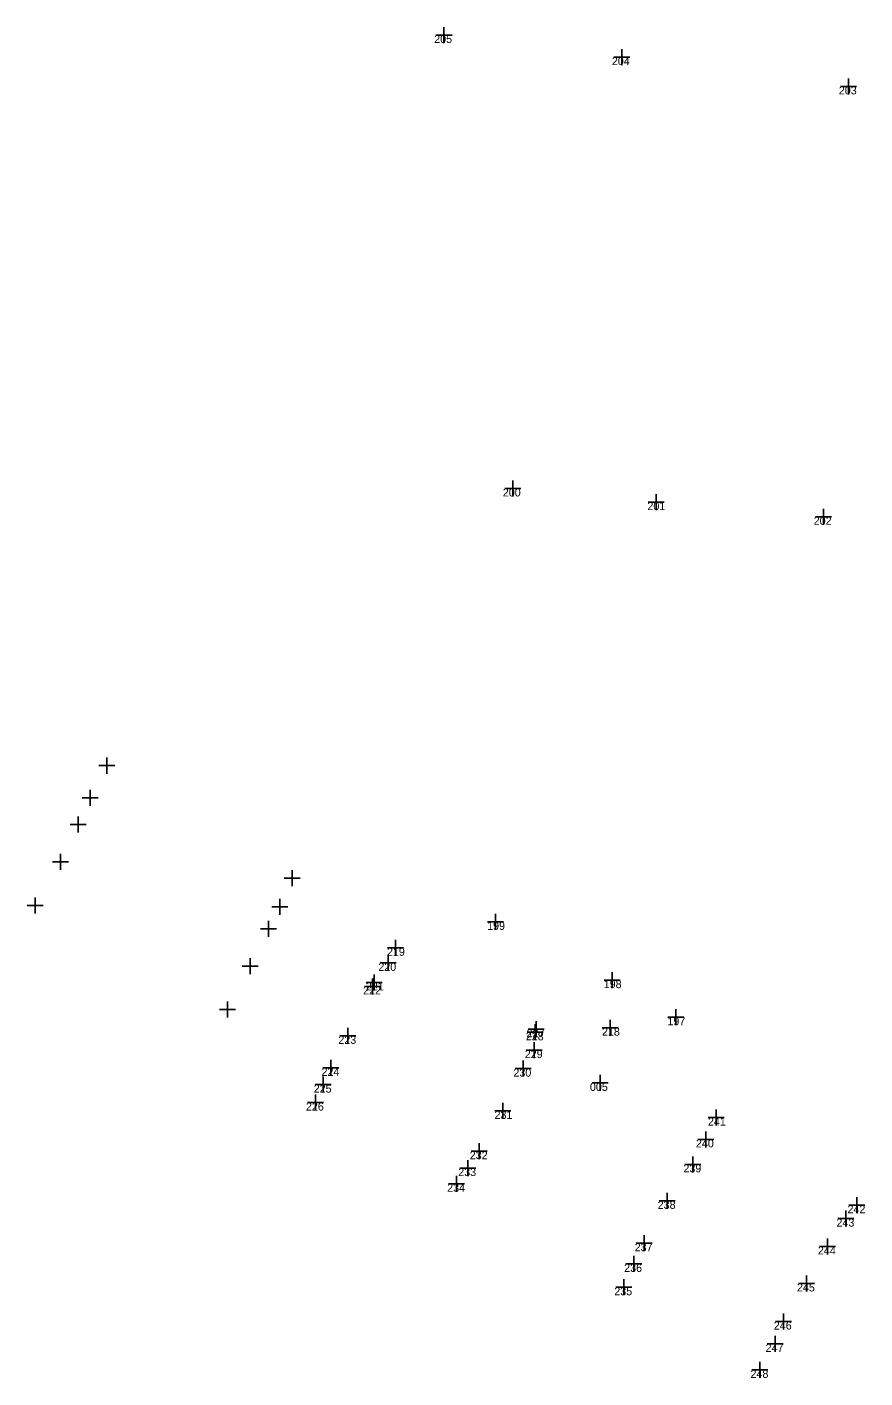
# Model space of a CAD drawing. Extents: x -706631 to -706106, y -1036183 to -1035074.
# Drawn here: x -706294.5 to -706242.2, y -1036182.5 to -1036098.1 of the extents above; entities that cross this region are included whole.
import ezdxf

# ---------------------------------------------------------------- set-up
doc = ezdxf.new("R2010")
doc.units = 0
doc.layers.add('čísla bodu', color=7, linetype='Continuous')

msp = doc.modelspace()

# ---------------------------------------------------------------- linework, layer by layer
at = {"layer": 'čísla bodu'}
for p, q in [((-706268.95, -1036098.6), (-706267.95, -1036098.6)), ((-706268.45, -1036099.1), (-706268.45, -1036098.1)), ((-706268.45, -1036098.6), (-706268.45, -1036098.6)), ((-706257.35, -1036100.48), (-706257.35, -1036099.48)), ((-706257.85, -1036099.98), (-706256.85, -1036099.98)), ((-706257.35, -1036099.98), (-706257.35, -1036099.98)), ((-706243.17, -1036102.31), (-706243.17, -1036101.31)), ((-706243.67, -1036101.81), (-706242.67, -1036101.81)), ((-706243.17, -1036101.81), (-706243.17, -1036101.81)), ((-706264.14, -1036127.43), (-706264.14, -1036126.43)), ((-706264.64, -1036126.93), (-706263.64, -1036126.93)), ((-706264.14, -1036126.93), (-706264.14, -1036126.93)), ((-706255.2, -1036128.28), (-706255.2, -1036127.28)), ((-706255.7, -1036127.78), (-706254.7, -1036127.78)), ((-706255.2, -1036127.78), (-706255.2, -1036127.78)), ((-706244.74, -1036129.2), (-706244.74, -1036128.2)), ((-706245.24, -1036128.7), (-706244.24, -1036128.7)), ((-706244.74, -1036128.7), (-706244.74, -1036128.7)), ((-706290.01, -1036144.25), (-706289.01, -1036144.25)), ((-706290.01, -1036144.25), (-706289.01, -1036144.25)), ((-706289.51, -1036144.75), (-706289.51, -1036143.75)), ((-706289.51, -1036144.75), (-706289.51, -1036143.75)), ((-706289.51, -1036144.25), (-706289.51, -1036144.25)), ((-706289.51, -1036144.25), (-706289.51, -1036144.25)), ((-706290.56, -1036146.76), (-706290.56, -1036145.76)), ((-706290.56, -1036146.76), (-706290.56, -1036145.76)), ((-706291.06, -1036146.26), (-706290.06, -1036146.26)), ((-706291.06, -1036146.26), (-706290.06, -1036146.26)), ((-706290.56, -1036146.26), (-706290.56, -1036146.26)), ((-706290.56, -1036146.26), (-706290.56, -1036146.26)), ((-706291.3, -1036148.43), (-706291.3, -1036147.43)), ((-706291.3, -1036148.43), (-706291.3, -1036147.43)), ((-706291.8, -1036147.93), (-706290.8, -1036147.93)), ((-706291.8, -1036147.93), (-706290.8, -1036147.93)), ((-706291.3, -1036147.93), (-706291.3, -1036147.93)), ((-706291.3, -1036147.93), (-706291.3, -1036147.93)), ((-706292.9, -1036150.26), (-706291.9, -1036150.26)), ((-706292.9, -1036150.26), (-706291.9, -1036150.26)), ((-706292.4, -1036150.76), (-706292.4, -1036149.76)), ((-706292.4, -1036150.76), (-706292.4, -1036149.76)), ((-706292.4, -1036150.26), (-706292.4, -1036150.26)), ((-706292.4, -1036150.26), (-706292.4, -1036150.26)), ((-706277.93, -1036151.77), (-706277.93, -1036150.77)), ((-706277.93, -1036151.77), (-706277.93, -1036150.77)), ((-706278.43, -1036151.27), (-706277.43, -1036151.27)), ((-706278.43, -1036151.27), (-706277.43, -1036151.27)), ((-706277.93, -1036151.27), (-706277.93, -1036151.27)), ((-706277.93, -1036151.27), (-706277.93, -1036151.27)), ((-706294, -1036153.49), (-706294, -1036152.49)), ((-706294, -1036153.49), (-706294, -1036152.49)), ((-706278.7, -1036153.57), (-706278.7, -1036152.57)), ((-706278.7, -1036153.57), (-706278.7, -1036152.57)), ((-706294.5, -1036152.99), (-706293.5, -1036152.99)), ((-706294.5, -1036152.99), (-706293.5, -1036152.99)), ((-706294, -1036152.99), (-706294, -1036152.99)), ((-706294, -1036152.99), (-706294, -1036152.99)), ((-706279.2, -1036153.07), (-706278.2, -1036153.07)), ((-706279.2, -1036153.07), (-706278.2, -1036153.07)), ((-706278.7, -1036153.07), (-706278.7, -1036153.07)), ((-706278.7, -1036153.07), (-706278.7, -1036153.07)), ((-706265.23, -1036154.51), (-706265.23, -1036153.51)), ((-706279.92, -1036154.44), (-706278.92, -1036154.44)), ((-706279.92, -1036154.44), (-706278.92, -1036154.44)), ((-706279.42, -1036154.94), (-706279.42, -1036153.94)), ((-706279.42, -1036154.94), (-706279.42, -1036153.94)), ((-706279.42, -1036154.44), (-706279.42, -1036154.44)), ((-706279.42, -1036154.44), (-706279.42, -1036154.44)), ((-706265.73, -1036154.01), (-706264.73, -1036154.01)), ((-706265.23, -1036154.01), (-706265.23, -1036154.01)), ((-706271.49, -1036156.13), (-706271.49, -1036155.13)), ((-706271.99, -1036155.63), (-706270.99, -1036155.63)), ((-706271.94, -1036157.07), (-706271.94, -1036156.07)), ((-706271.49, -1036155.63), (-706271.49, -1036155.63)), ((-706281.05, -1036156.78), (-706280.05, -1036156.78)), ((-706281.05, -1036156.78), (-706280.05, -1036156.78)), ((-706280.55, -1036157.28), (-706280.55, -1036156.28)), ((-706280.55, -1036157.28), (-706280.55, -1036156.28)), ((-706280.55, -1036156.78), (-706280.55, -1036156.78)), ((-706280.55, -1036156.78), (-706280.55, -1036156.78)), ((-706272.44, -1036156.57), (-706271.44, -1036156.57)), ((-706271.94, -1036156.57), (-706271.94, -1036156.57)), ((-706273.31, -1036157.79), (-706272.31, -1036157.79)), ((-706272.91, -1036158.54), (-706272.91, -1036157.54)), ((-706272.81, -1036158.29), (-706272.81, -1036157.29)), ((-706272.81, -1036157.79), (-706272.81, -1036157.79)), ((-706258.45, -1036157.65), (-706257.45, -1036157.65)), ((-706257.95, -1036158.15), (-706257.95, -1036157.15)), ((-706257.95, -1036157.65), (-706257.95, -1036157.65)), ((-706273.41, -1036158.04), (-706272.41, -1036158.04)), ((-706272.91, -1036158.04), (-706272.91, -1036158.04)), ((-706282.48, -1036159.49), (-706281.48, -1036159.49)), ((-706282.48, -1036159.49), (-706281.48, -1036159.49)), ((-706281.98, -1036159.99), (-706281.98, -1036158.99)), ((-706281.98, -1036159.99), (-706281.98, -1036158.99)), ((-706281.98, -1036159.49), (-706281.98, -1036159.49)), ((-706281.98, -1036159.49), (-706281.98, -1036159.49)), ((-706253.97, -1036160.47), (-706253.97, -1036159.47)), ((-706262.75, -1036161.41), (-706262.75, -1036160.41)), ((-706262.7, -1036161.22), (-706262.7, -1036160.22)), ((-706258.06, -1036161.12), (-706258.06, -1036160.12)), ((-706254.47, -1036159.97), (-706253.47, -1036159.97)), ((-706253.97, -1036159.97), (-706253.97, -1036159.97)), ((-706274.96, -1036161.13), (-706273.96, -1036161.13)), ((-706274.46, -1036161.63), (-706274.46, -1036160.63)), ((-706274.46, -1036161.13), (-706274.46, -1036161.13)), ((-706263.25, -1036160.91), (-706262.25, -1036160.91)), ((-706263.2, -1036160.72), (-706262.2, -1036160.72)), ((-706262.75, -1036160.91), (-706262.75, -1036160.91)), ((-706262.7, -1036160.72), (-706262.7, -1036160.72)), ((-706258.56, -1036160.62), (-706257.56, -1036160.62)), ((-706258.06, -1036160.62), (-706258.06, -1036160.62)), ((-706263.31, -1036162.02), (-706262.31, -1036162.02)), ((-706262.81, -1036162.52), (-706262.81, -1036161.52)), ((-706262.81, -1036162.02), (-706262.81, -1036162.02)), ((-706275.51, -1036163.63), (-706275.51, -1036162.63)), ((-706263.5, -1036163.68), (-706263.5, -1036162.68)), ((-706276.01, -1036163.13), (-706275.01, -1036163.13)), ((-706276, -1036164.68), (-706276, -1036163.68)), ((-706275.51, -1036163.13), (-706275.51, -1036163.13)), ((-706264, -1036163.18), (-706263, -1036163.18)), ((-706263.5, -1036163.18), (-706263.5, -1036163.18)), ((-706258.7, -1036164.57), (-706258.7, -1036163.57)), ((-706276.5, -1036164.18), (-706275.5, -1036164.18)), ((-706276, -1036164.18), (-706276, -1036164.18)), ((-706259.2, -1036164.07), (-706258.2, -1036164.07)), ((-706258.7, -1036164.07), (-706258.7, -1036164.07)), ((-706276.97, -1036165.3), (-706275.97, -1036165.3)), ((-706276.47, -1036165.8), (-706276.47, -1036164.8)), ((-706276.47, -1036165.3), (-706276.47, -1036165.3)), ((-706264.77, -1036166.32), (-706264.77, -1036165.32)), ((-706265.27, -1036165.82), (-706264.27, -1036165.82)), ((-706264.77, -1036165.82), (-706264.77, -1036165.82)), ((-706251.94, -1036166.24), (-706250.94, -1036166.24)), ((-706251.44, -1036166.74), (-706251.44, -1036165.74)), ((-706251.44, -1036166.24), (-706251.44, -1036166.24)), ((-706252.1, -1036168.1), (-706252.1, -1036167.1)), ((-706266.25, -1036168.84), (-706266.25, -1036167.84)), ((-706252.6, -1036167.6), (-706251.6, -1036167.6)), ((-706252.1, -1036167.6), (-706252.1, -1036167.6)), ((-706266.75, -1036168.34), (-706265.75, -1036168.34)), ((-706266.25, -1036168.34), (-706266.25, -1036168.34)), ((-706252.9, -1036169.66), (-706252.9, -1036168.66)), ((-706267.47, -1036169.39), (-706266.47, -1036169.39)), ((-706266.97, -1036169.89), (-706266.97, -1036168.89)), ((-706266.97, -1036169.39), (-706266.97, -1036169.39)), ((-706253.4, -1036169.16), (-706252.4, -1036169.16)), ((-706252.9, -1036169.16), (-706252.9, -1036169.16)), ((-706268.16, -1036170.37), (-706267.16, -1036170.37)), ((-706267.66, -1036170.87), (-706267.66, -1036169.87)), ((-706267.66, -1036170.37), (-706267.66, -1036170.37)), ((-706254.51, -1036171.94), (-706254.51, -1036170.94)), ((-706242.65, -1036172.21), (-706242.65, -1036171.21)), ((-706255.01, -1036171.44), (-706254.01, -1036171.44)), ((-706254.51, -1036171.44), (-706254.51, -1036171.44)), ((-706243.34, -1036173.05), (-706243.34, -1036172.05)), ((-706243.15, -1036171.71), (-706242.15, -1036171.71)), ((-706242.65, -1036171.71), (-706242.65, -1036171.71)), ((-706243.84, -1036172.55), (-706242.84, -1036172.55)), ((-706243.34, -1036172.55), (-706243.34, -1036172.55)), ((-706255.95, -1036174.59), (-706255.95, -1036173.59)), ((-706244.5, -1036174.79), (-706244.5, -1036173.79)), ((-706256.45, -1036174.09), (-706255.45, -1036174.09)), ((-706255.95, -1036174.09), (-706255.95, -1036174.09)), ((-706245, -1036174.29), (-706244, -1036174.29)), ((-706244.5, -1036174.29), (-706244.5, -1036174.29)), ((-706257.09, -1036175.38), (-706256.09, -1036175.38)), ((-706256.59, -1036175.88), (-706256.59, -1036174.88)), ((-706256.59, -1036175.38), (-706256.59, -1036175.38)), ((-706257.22, -1036177.34), (-706257.22, -1036176.34)), ((-706245.81, -1036177.1), (-706245.81, -1036176.1)), ((-706257.72, -1036176.84), (-706256.72, -1036176.84)), ((-706257.22, -1036176.84), (-706257.22, -1036176.84)), ((-706246.31, -1036176.6), (-706245.31, -1036176.6)), ((-706245.81, -1036176.6), (-706245.81, -1036176.6)), ((-706247.74, -1036178.98), (-706246.74, -1036178.98)), ((-706247.24, -1036179.48), (-706247.24, -1036178.48)), ((-706247.24, -1036178.98), (-706247.24, -1036178.98)), ((-706248.27, -1036180.38), (-706247.27, -1036180.38)), ((-706247.77, -1036180.88), (-706247.77, -1036179.88)), ((-706247.77, -1036180.38), (-706247.77, -1036180.38)), ((-706248.71, -1036182.5), (-706248.71, -1036181.5)), ((-706249.21, -1036182), (-706248.21, -1036182)), ((-706248.71, -1036182), (-706248.71, -1036182))]:
    msp.add_line(p, q, dxfattribs=at)

# ---------------------------------------------------------------- texts
for s, p in [('205', (-706269.062, -1036099.1)), ('204', (-706257.962, -1036100.48)), ('203', (-706243.782, -1036102.31)), ('200', (-706264.774, -1036127.43)), ('201', (-706255.742, -1036128.28)), ('202', (-706245.352, -1036129.2)), ('199', (-706265.754, -1036154.51)), ('219', (-706272.012, -1036156.13)), ('220', (-706272.552, -1036157.07)), ('221', (-706273.331, -1036158.29)), ('198', (-706258.472, -1036158.15)), ('222', (-706273.5, -1036158.54)), ('197', (-706254.492, -1036160.47)), ('223', (-706275.05, -1036161.63)), ('228', (-706263.34, -1036161.41)), ('227', (-706263.29, -1036161.22)), ('218', (-706258.58, -1036161.12)), ('229', (-706263.402, -1036162.52)), ('224', (-706276.1, -1036163.63)), ('230', (-706264.112, -1036163.68)), ('225', (-706276.59, -1036164.68)), ('005', (-706259.334, -1036164.57)), ('226', (-706277.074, -1036165.8)), ('231', (-706265.291, -1036166.32)), ('241', (-706251.961, -1036166.74)), ('240', (-706252.712, -1036168.1)), ('232', (-706266.84, -1036168.84)), ('233', (-706267.56, -1036169.89)), ('239', (-706253.492, -1036169.66)), ('234', (-706268.25, -1036170.87)), ('238', (-706255.1, -1036171.94)), ('242', (-706243.24, -1036172.21)), ('243', (-706243.93, -1036173.05)), ('237', (-706256.54, -1036174.59)), ('244', (-706245.09, -1036174.79)), ('236', (-706257.194, -1036175.88)), ('235', (-706257.81, -1036177.34)), ('245', (-706246.4, -1036177.1)), ('246', (-706247.844, -1036179.48)), ('247', (-706248.36, -1036180.88)), ('248', (-706249.3, -1036182.5))]:
    msp.add_text(s, height=0.5, dxfattribs=at).set_placement(p)

doc.saveas('drawing.dxf')
